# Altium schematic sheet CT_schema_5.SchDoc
size 309 x 321 mm
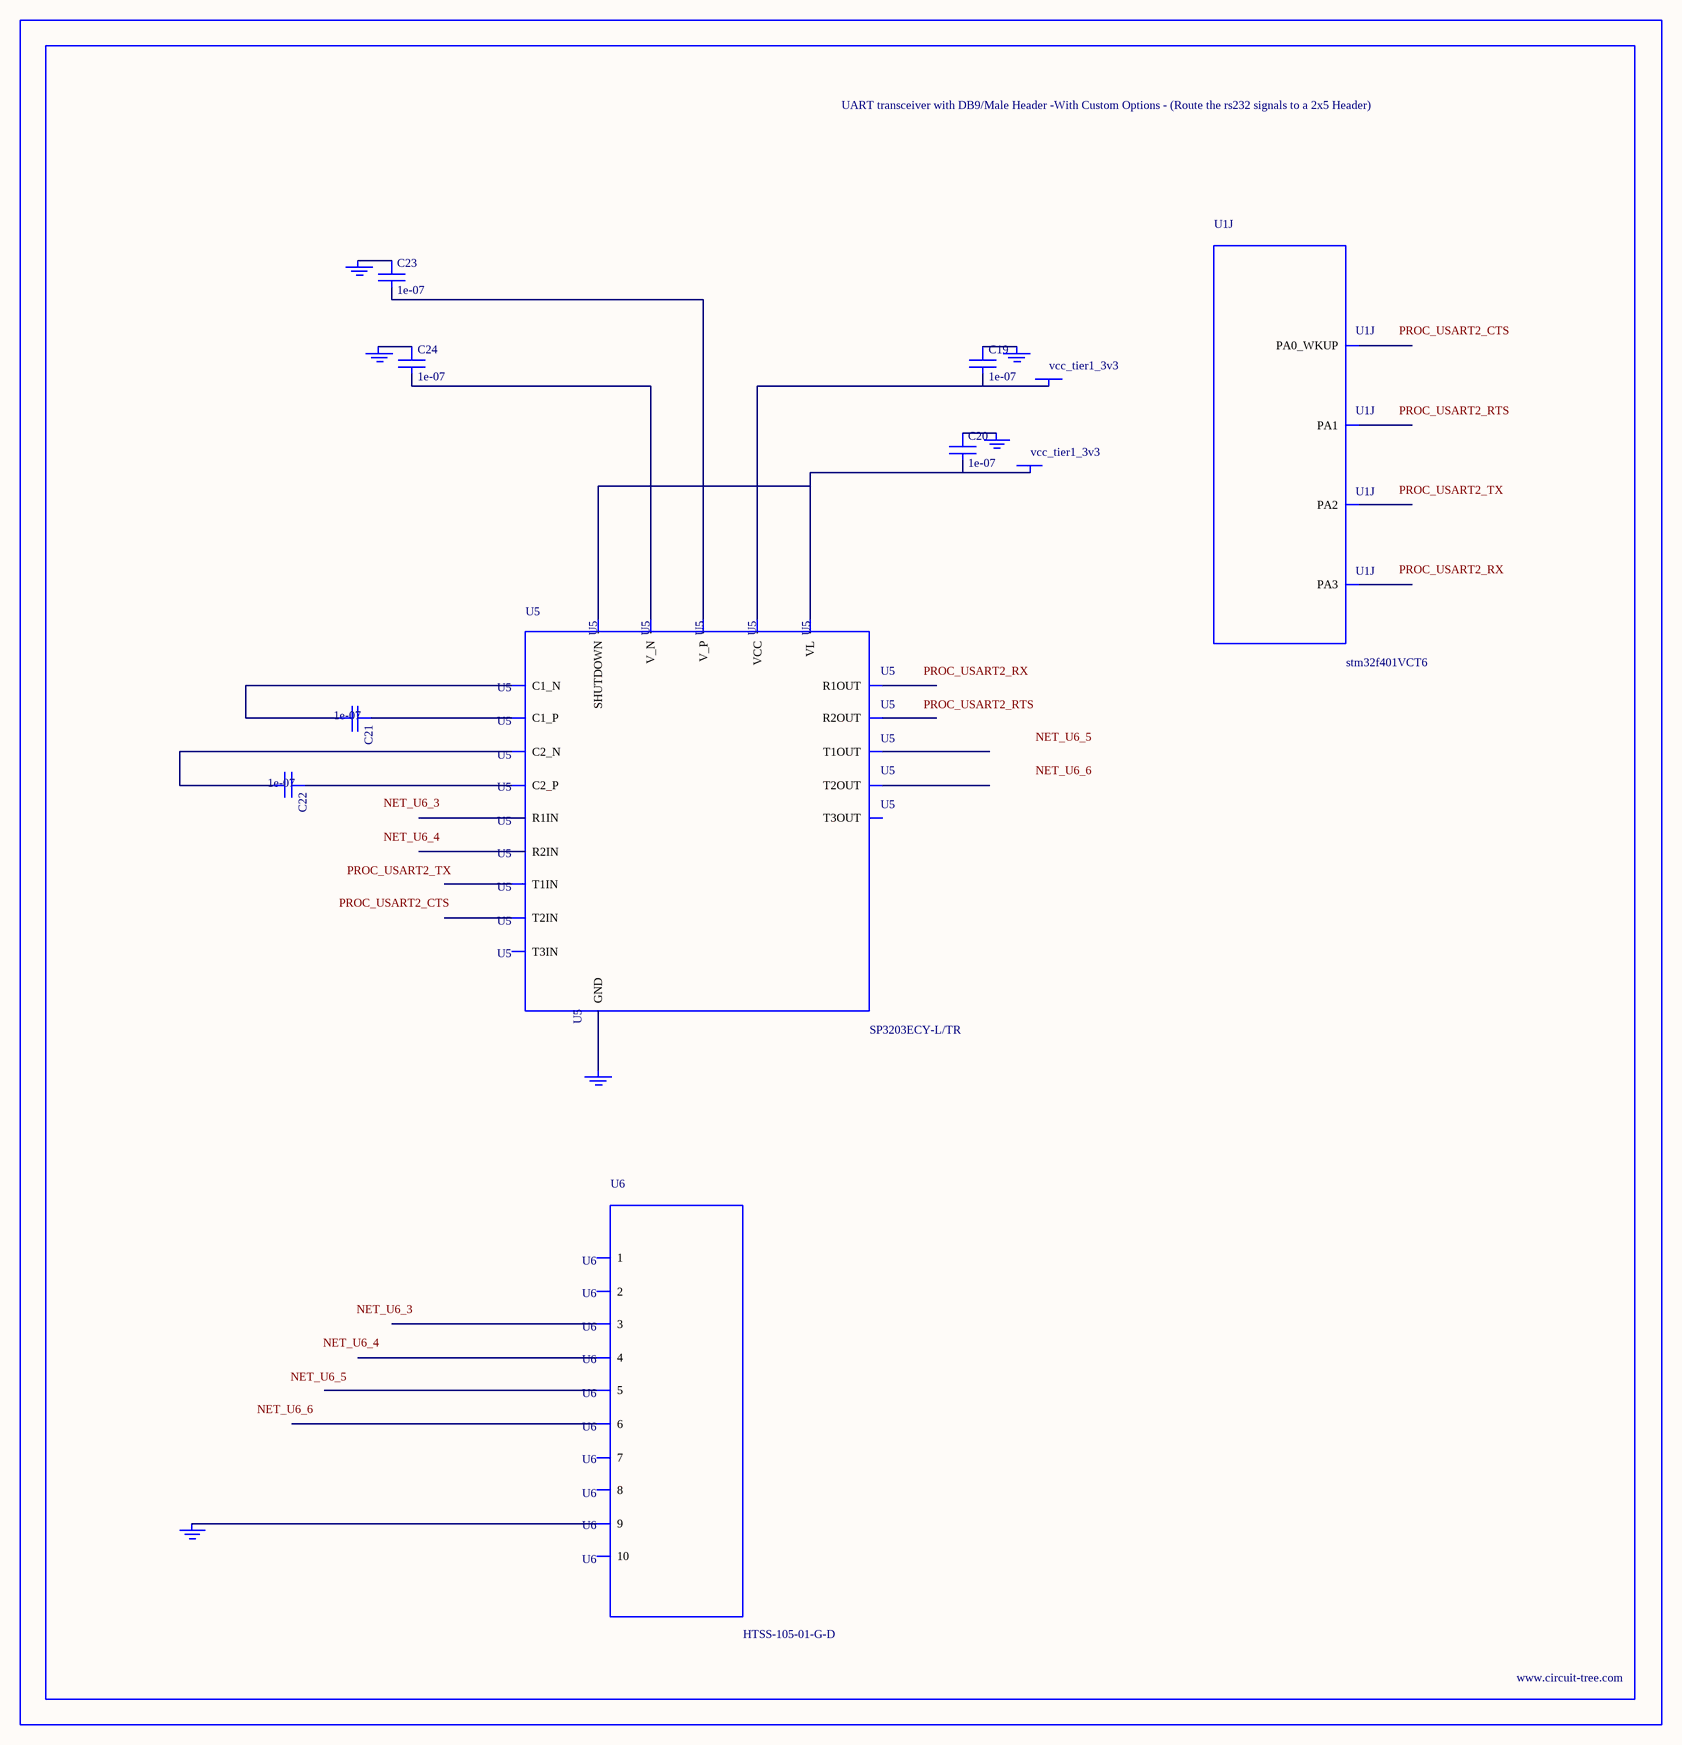
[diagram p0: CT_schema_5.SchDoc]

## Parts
BORDER4  (no value)
C19  1e-07  [C0402]
C20  1e-07  [C0402]
C21  1e-07  [C0402]
C22  1e-07  [C0402]
C23  1e-07  [C0402]
C24  1e-07  [C0402]
GND_INSTANCE_4_0  (no value)
GND_INSTANCE_4_1  (no value)
GND_INSTANCE_4_2  (no value)
GND_INSTANCE_4_3  (no value)
GND_INSTANCE_4_4  (no value)
GND_INSTANCE_4_5  (no value)
POWER_INSTANCE_4_0  vcc_tier1_3v3
POWER_INSTANCE_4_1  vcc_tier1_3v3
U1  stm32f401VCT6  [LQFP100]  (part J of 11)
U5  SP3203ECY-L/TR  [TSSOP20-I]
U6  HTSS-105-01-G-D  [HTSS-105-01-G-D]

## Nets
NetC19_1: C19.1 GND_INSTANCE_4_3.0(GND)
NetC19_2: C19.2 POWER_INSTANCE_4_1.0(PWR) U5.19(VCC)
NetC20_1: C20.1 GND_INSTANCE_4_2.0(GND)
NetC20_2: C20.2 POWER_INSTANCE_4_0.0(PWR) U5.12(VL) U5.20(SHUTDOWN)
NetC21_1: C21.1 U5.1(C1_P)
NetC21_2: C21.2 U5.3(C1_N)
NetC22_1: C22.1 U5.4(C2_P)
NetC22_2: C22.2 U5.5(C2_N)
NetC23_1: C23.1 GND_INSTANCE_4_0.0(GND)
NetC23_2: C23.2 U5.2(V_P)
NetC24_1: C24.1 GND_INSTANCE_4_1.0(GND)
NetC24_2: C24.2 U5.6(V_N)
NetGND_INSTANCE_4_4_0: GND_INSTANCE_4_4.0(GND) U5.18(GND)
NetGND_INSTANCE_4_5_0: GND_INSTANCE_4_5.0(GND) U6.9

Not connected (* = marked no-connect by the designer): U1 23(PA0_WKUP) 24(PA1) 25(PA2) 26(PA3); U5 7(T1IN) 8(T2IN) 9(T3IN) 10(R2OUT) 11(R1OUT) 13(R2IN) 14(R1IN) 15(T3OUT) 16(T2OUT) 17(T1OUT); U6 1 2 3 4 5 6 7 8 10

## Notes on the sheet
- Labels drawn without touching a wire or pin: NET_U6_3, NET_U6_4, NET_U6_5, NET_U6_6, PROC_USART2_CTS, PROC_USART2_RTS, PROC_USART2_RX, PROC_USART2_TX

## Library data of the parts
BORDER4 = BORDER_PAGE4
C19-C24 = C0402C104K3RACTU
GND_INSTANCE_4_0-GND_INSTANCE_4_5 = GND
POWER_INSTANCE_4_0 POWER_INSTANCE_4_1 = PWR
